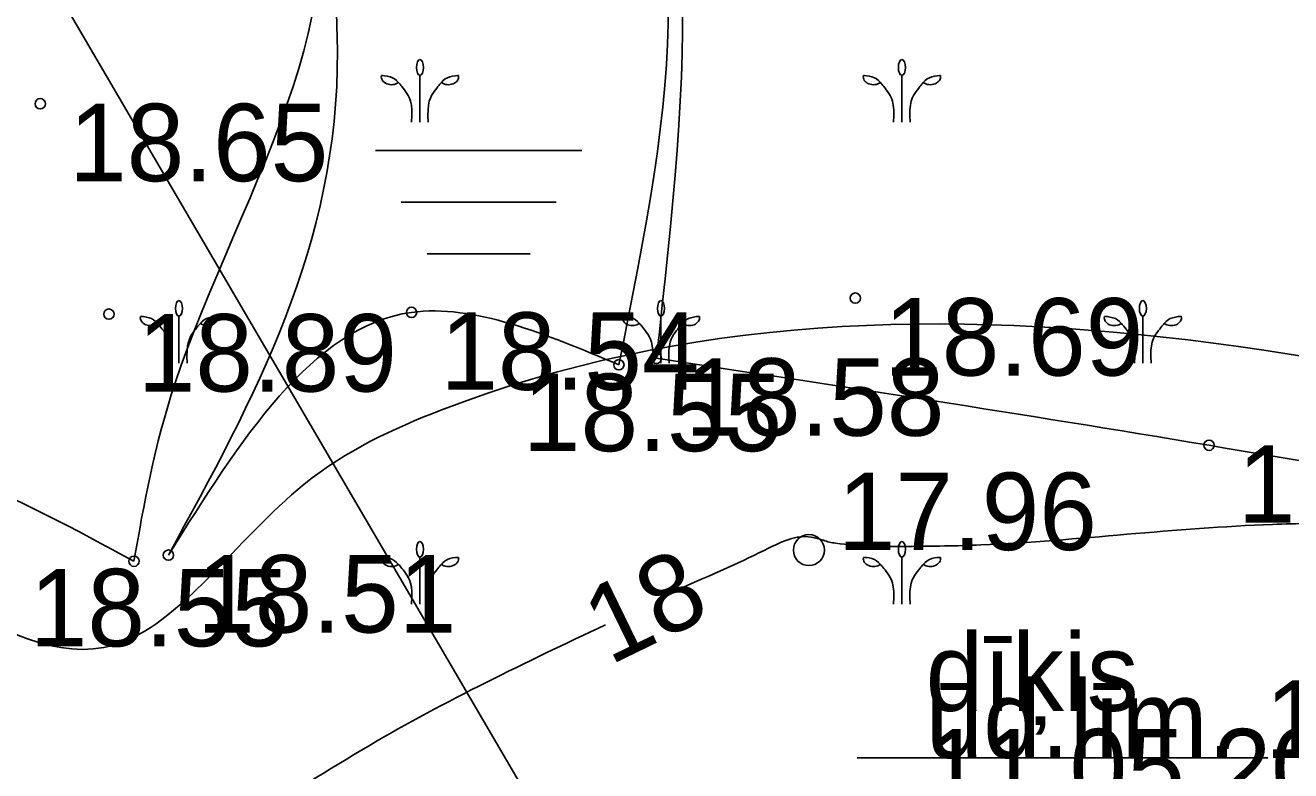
# Model space of a CAD drawing. Extents: x 521824 to 524158, y 294774 to 296228.
# Drawn here: x 522068.27 to 522086.65, y 295999.58 to 296010.41 of the extents above; entities that cross this region are included whole.
import ezdxf

# ---------------------------------------------------------------- set-up
doc = ezdxf.new("R2010")
doc.units = 0
for name, color, linetype in [('GL Aizsargjoslas', 7, 'Continuous'), ('HIDG_AATZ_####_TKST_#', 7, 'Continuous'), ('HIDG_ELEM_####_####_#', 7, 'Continuous'), ('HIDG_HORZ_####_TKST_#', 7, 'Continuous'), ('HIDG_HORZ_PAMT_####_#', 7, 'Continuous'), ('HIDG_HORZ_RESN_####_#', 7, 'Continuous'), ('HIDG_HPAS_####_TKST_#', 7, 'Continuous'), ('HIDG_NLIN_####_####_#', 7, 'Continuous'), ('HIDG_PLIN_####_####_#', 7, 'Continuous'), ('HIDG_UATZ_####_TKST_#', 7, 'Continuous'), ('RELJ_AATZ_####_TKST_#', 7, 'Continuous'), ('RELJ_ELEM_####_####_#', 7, 'Continuous'), ('RELJ_HORZ_PAMT_####_#', 7, 'Continuous'), ('RELJ_NOGA_####_####_#', 7, 'Continuous'), ('RELJ_NOGL_####_####_#', 7, 'Continuous'), ('TERT_ELEM_####_####_#', 7, 'Continuous'), ('TERT_KONT_####_####_#', 7, 'Continuous')]:
    doc.layers.add(name, color=color, linetype=linetype)

msp = doc.modelspace()

# ---------------------------------------------------------------- linework, layer by layer
at = {"layer": 'GL Aizsargjoslas'}
msp.add_lwpolyline([(522131.428, 295816.081), (522115.494, 295836.896), (522093.246, 295865.959), (522070.658, 295896.651), (522048.069, 295927.342), (522034.295, 295950.909), (522016.445, 295981.452), (522014.167, 295985.351), (522007.117, 295997.907), (522041.36, 296024.307), (522061.861, 296026.336), (522066.449, 296014.804), (522085.298, 295982.553), (522098.69, 295959.638), (522141.234, 295901.981), (522163.309, 295873.143), (522185.385, 295844.305), (522186.608, 295842.871), (522172.848, 295833.392), (522161.563, 295826.069), (522160.802, 295825.572), (522154.447, 295832.015)], close=True, dxfattribs=at)
at = {"layer": 'HIDG_ELEM_####_####_#'}
msp.add_circle((522079.65, 296002.784), 0.225, dxfattribs=at)
at = {"layer": 'HIDG_HORZ_PAMT_####_#'}
msp.add_spline([(522097.456, 296003.003), (522098.42, 296003.112), (522098.886, 296003.109), (522101.493, 296002.854), (522104.863, 296002.829), (522105.455, 296002.546), (522105.764, 296002.03), (522106.434, 296001.103), (522105.073, 295999.884), (522105.328, 295997.947), (522105.313, 295997.082), (522105.495, 295995.289), (522105.536, 295995.052), (522105.782, 295994.342), (522106.713, 295993.946), (522107.552, 295993.546), (522108.149, 295993.448), (522108.619, 295991.553), (522108.577, 295991.344), (522108.448, 295991.154), (522106.283, 295991.375), (522105.272, 295992.2), (522104.189, 295992.719), (522103.543, 295992.913), (522103.242, 295993.07), (522101.964, 295993.08), (522101.329, 295993.113), (522100.932, 295993.02), (522099.761, 295992.856), (522098.335, 295992.439), (522097.436, 295991.876), (522096.287, 295991.458), (522094.937, 295990.58), (522094.192, 295990.336), (522093.424, 295990.187), (522091.553, 295990.123), (522089.682, 295990.202), (522089.358, 295990.216), (522085.744, 295990.713), (522081.631, 295990.342), (522080.807, 295990.11), (522079.09, 295989.003), (522078.197, 295988.522), (522077.728, 295988.334), (522077.237, 295988.193), (522076.001, 295988.101), (522074.761, 295988.259), (522072.524, 295989.01), (522071.862, 295989.025), (522071.249, 295988.887), (522068.367, 295988.362), (522067.498, 295988.56), (522067.064, 295988.714), (522066.631, 295988.911), (522064.566, 295990.452), (522063.244, 295992.536), (522063.001, 295993.19), (522062.602, 295994.158), (522059.484, 295999.35), (522058.893, 296002.168), (522061.43, 296003.805), (522064.048, 296003.805), (522069.557, 296001.404), (522072.32, 296003.741), (522074.302, 296004.815), (522097.456, 296003.003)], degree=3, dxfattribs=at)
at = {"layer": 'HIDG_HORZ_RESN_####_#'}
for points in [[(522094.419, 295993.471), (522094.954, 295993.565), (522096.238, 295993.964), (522096.688, 295994.186), (522097.131, 295994.417), (522098.003, 295994.902), (522102.207, 295997.326), (522102.626, 295997.566), (522102.825, 295997.714), (522102.923, 295997.807), (522103.019, 295997.916), (522103.273, 295998.318), (522103.415, 295998.724), (522103.479, 295999.13), (522103.502, 295999.536), (522103.508, 295999.817), (522103.478, 296000.105), (522103.377, 296000.379), (522103.288, 296000.505), (522103.232, 296000.564), (522103.2, 296000.593), (522103.167, 296000.621), (522102.833, 296000.797), (522102.499, 296000.851), (522102.165, 296000.855), (522101.998, 296000.861), (522101.831, 296000.881), (522097.302, 296001.725), (522092.769, 296002.559), (522091.705, 296002.733), (522090.637, 296002.875), (522089.566, 296002.996), (522088.495, 296003.106), (522087.442, 296003.168), (522086.385, 296003.157), (522084.265, 296003.013), (522082.146, 296002.859), (522081.089, 296002.838), (522080.036, 296002.885), (522079.947, 296002.9), (522079.86, 296002.926), (522079.772, 296002.952), (522079.684, 296002.97), (522079.499, 296002.974), (522079.462, 296002.967), (522078.999, 296002.779), (522077.795, 296002.233)], [(522076.693, 296001.698), (522073.251, 295999.937), (522069.684, 295998.285), (522069.633, 295998.28), (522069.496, 295998.301), (522069.359, 295998.339), (522069.222, 295998.38), (522069.086, 295998.409), (522068.72, 295998.453), (522068.449, 295998.318), (522068.414, 295998.223), (522068.385, 295998.128), (522068.338, 295997.938), (522068.282, 295997.558), (522068.247, 295997.178), (522068.2, 295996.798), (522067.729, 295994.059), (522067.268, 295991.321), (522067.299, 295990.913), (522067.497, 295990.535), (522067.816, 295990.195), (522068.007, 295990.042), (522068.108, 295989.971), (522068.212, 295989.903), (522068.971, 295989.627), (522069.729, 295989.648), (522070.549, 295989.787), (522073.982, 295990.519), (522074.567, 295990.609), (522075.157, 295990.665), (522075.749, 295990.722), (522076.337, 295990.814), (522076.713, 295990.923), (522077.072, 295991.098), (522077.582, 295991.652), (522078.55, 295993.97), (522080.388, 295998.378), (522080.481, 295998.539), (522080.583, 295998.609), (522080.81, 295998.515), (522081.314, 295997.644), (522081.814, 295996.353), (522082.223, 295995.227), (522083.472, 295992.047)]]:
    msp.add_spline(points, degree=3, dxfattribs=at)
at = {"layer": 'HIDG_NLIN_####_####_#'}
for points in [[(522069.847, 296002.621), (522070.445, 296005.213), (522071.843, 296012.882), (522070.004, 296013.804), (522068.327, 296014.681), (522064.837, 296015.835), (522066.863, 296015.976), (522068.488, 296015.043), (522072.507, 296013.382), (522076.21, 296014.002), (522077.435, 296005.57)], [(522070.346, 296002.711), (522072.801, 296010.037), (522073.155, 296012.721), (522075.854, 296013.462), (522076.89, 296005.476)]]:
    msp.add_spline(points, degree=3, dxfattribs=at)
at = {"layer": 'HIDG_PLIN_####_####_#'}
for points in [[(522070.346, 296002.711), (522073.878, 296006.237), (522076.89, 296005.476)], [(522077.435, 296005.57), (522085.461, 296004.306), (522098.512, 296003.392), (522105.395, 296003.443), (522107.83, 296000.993), (522105.638, 295997.677), (522105.744, 295995.487), (522109.498, 295993.85), (522109.498, 295989.848), (522114.208, 295986.087), (522123.878, 295989.299), (522133.271, 295980.049), (522137.318, 295976.793), (522131.563, 295972.766), (522130.654, 295969.62), (522124.01, 295968.477), (522115.857, 295969.771), (522111.112, 295969.734), (522110.471, 295975.549), (522112.358, 295978.857), (522112.409, 295984.266), (522101.265, 295992.806), (522096.41, 295991.057), (522092.914, 295989.062)], [(522092.914, 295989.062), (522089.457, 295989.995), (522081.185, 295989.929), (522077.718, 295986.793), (522072.195, 295988.487), (522065.261, 295988.052), (522062.418, 295992.785), (522058.951, 295999.177), (522057.619, 296001.908), (522064.008, 296004.575), (522069.847, 296002.621)]]:
    msp.add_spline(points, degree=3, dxfattribs=at)
at = {"layer": 'HIDG_UATZ_####_TKST_#'}
msp.add_lwpolyline([(522080.35, 295999.765), (522086.316, 295999.765)], dxfattribs=at)
at = {"layer": 'RELJ_ELEM_####_####_#'}
for centre in [(522068.486, 296009.268), (522080.324, 296006.444), (522073.878, 296006.237), (522069.483, 296006.212), (522077.435, 296005.57), (522076.89, 296005.476), (522085.461, 296004.306), (522069.847, 296002.621), (522070.346, 296002.711)]:
    msp.add_circle(centre, 0.075, dxfattribs=at)
at = {"layer": 'RELJ_HORZ_PAMT_####_#'}
for points in [[(522147.001, 296013.879), (522145.334, 296014.111), (522144.908, 296014.079), (522138.003, 296012.088), (522137.814, 296012.008), (522135.146, 296011.271), (522131.635, 296010.287), (522130.341, 296009.639), (522127.864, 296009.75), (522127.714, 296009.761), (522127.564, 296009.8), (522127.264, 296009.832), (522127.105, 296009.79), (522126.615, 296009.677), (522125.425, 296009.552), (522124.235, 296009.457), (522121.853, 296009.334), (522117.084, 296009.201), (522116.821, 296009.194), (522115.322, 296009.109), (522113.823, 296009.021), (522110.825, 296008.845), (522106.552, 296008.587), (522106.42, 296008.498), (522105.24, 296008.381), (522103.71, 296008.042), (522102.575, 296008.01), (522101.436, 296008.101), (522100.295, 296008.227), (522099.156, 296008.295), (522097.506, 296008.302), (522096.685, 296008.185), (522096.274, 296008.062), (522096.069, 296007.981), (522095.864, 296007.884), (522092.757, 296008.408), (522089.948, 296009.718), (522091.502, 296010.619), (522091.012, 296011.544), (522089.457, 296012.256), (522087.875, 296012.556), (522086.266, 296013.266), (522086.078, 296014.194)], [(522045.999, 296008.938), (522046.495, 296008.926), (522047.557, 296008.988), (522048.735, 296009.162), (522050.109, 296009.512), (522050.809, 296009.677), (522052.34, 296009.896), (522053.693, 296010.101), (522054.536, 296010.335), (522054.996, 296010.355), (522055.848, 296010.249), (522056.362, 296010.052), (522056.844, 296009.797), (522057.323, 296009.545), (522057.827, 296009.353), (522058.463, 296009.222), (522059.039, 296009.168), (522060.322, 296008.975), (522060.946, 296008.772), (522061.254, 296008.62), (522061.558, 296008.425), (522061.883, 296008.015), (522062.022, 296007.524), (522062.054, 296007.162), (522062.019, 296006.801), (522061.435, 296005.355), (522061.1, 296005.14), (522060.764, 296004.933), (522060.089, 296004.536), (522058.739, 296003.753), (522057.792, 296003.234), (522057.321, 296002.952), (522057.086, 296002.788), (522056.969, 296002.698), (522056.853, 296002.602), (522056.584, 296002.103), (522056.588, 296001.531), (522056.86, 296000.048), (522057.24, 295998.543), (522057.746, 295997.71), (522058.037, 295997.317), (522058.303, 295996.91), (522059.043, 295995.576), (522059.759, 295994.23), (522060.122, 295993.338), (522060.406, 295992.406), (522060.729, 295991.496), (522060.944, 295991.069), (522061.213, 295990.67), (522061.49, 295990.366), (522061.793, 295990.09), (522062.252, 295989.683), (522062.396, 295989.538), (522064.208, 295987.613), (522065.338, 295986.418), (522065.918, 295985.834), (522066.525, 295985.268), (522067.242, 295984.881), (522068.074, 295984.734), (522068.945, 295984.657), (522069.37, 295984.591), (522069.777, 295984.479), (522071.163, 295983.949), (522071.837, 295983.615), (522072.507, 295983.186), (522073.445, 295982.313), (522074.19, 295981.299), (522074.759, 295980.263), (522075.171, 295979.327), (522075.146, 295979.012), (522074.869, 295978.709), (522073.887, 295978.125), (522072.886, 295977.541), (522072.584, 295977.238), (522072.525, 295976.923), (522072.6, 295976.687), (522072.713, 295976.422), (522073.008, 295976.004)]]:
    msp.add_spline(points, degree=3, dxfattribs=at)
at = {"layer": 'RELJ_NOGA_####_####_#'}
msp.add_spline([(522076.372, 295971.107), (522071.771, 295966.998), (522065.911, 295963.274), (522062.404, 295965.313), (522059.129, 295973.294), (522053.399, 295985.165), (522047.568, 295996.23), (522043.494, 296004.53), (522040.94, 296006.195), (522036.392, 296017.202), (522035.817, 296019.888)], degree=3, dxfattribs=at)
at = {"layer": 'RELJ_NOGL_####_####_#'}
msp.add_spline([(522076.372, 295971.107), (522070.977, 295968.839), (522067.829, 295967.468), (522065.228, 295970.581), (522062.385, 295977.993), (522058.471, 295985.855), (522053.108, 295997.011), (522048.49, 296007.412), (522045.541, 296009.219)], degree=3, dxfattribs=at)
at = {"layer": 'TERT_ELEM_####_####_#'}
for p, q in [((522074, 296009), (522074, 296009.681)), ((522074, 296009), (522074, 296009.681)), ((522081, 296009), (522081, 296009.681)), ((522081, 296009), (522081, 296009.681)), ((522073.353, 296008.588), (522076.353, 296008.588)), ((522073.728, 296007.838), (522075.978, 296007.838)), ((522074.103, 296007.088), (522075.603, 296007.088)), ((522070.5, 296005.5), (522070.5, 296006.181)), ((522070.5, 296005.5), (522070.5, 296006.181)), ((522077.5, 296005.5), (522077.5, 296006.181)), ((522077.5, 296005.5), (522077.5, 296006.181)), ((522084.5, 296005.5), (522084.5, 296006.181)), ((522084.5, 296005.5), (522084.5, 296006.181)), ((522074, 296002), (522074, 296002.681)), ((522074, 296002), (522074, 296002.681)), ((522081, 296002), (522081, 296002.681)), ((522081, 296002), (522081, 296002.681))]:
    msp.add_line(p, q, dxfattribs=at)
for centre in [(522074, 296009.795), (522074, 296009.795), (522081, 296009.795), (522081, 296009.795), (522070.5, 296006.295), (522070.5, 296006.295), (522077.5, 296006.295), (522077.5, 296006.295), (522084.5, 296006.295), (522084.5, 296006.295), (522074, 296002.795), (522074, 296002.795), (522081, 296002.795), (522081, 296002.795)]:
    msp.add_ellipse(centre, major_axis=(0, 0.114), ratio=0.447069, dxfattribs=at)
for centre, major_axis, start_param, end_param in [((522073.586, 296009.658), (-0.147, 0), 6.117242, 8.627806), ((522073.586, 296009.658), (-0.147, 0), 6.117242, 8.627806), ((522074.414, 296009.658), (0.147, 0), 3.938565, 6.449128), ((522074.414, 296009.658), (0.147, 0), 3.938565, 6.449128), ((522080.586, 296009.658), (-0.147, 0), 6.117242, 8.627806), ((522080.586, 296009.658), (-0.147, 0), 6.117242, 8.627806), ((522081.414, 296009.658), (0.147, 0), 3.938565, 6.449128), ((522081.414, 296009.658), (0.147, 0), 3.938565, 6.449128), ((522070.086, 296006.158), (-0.147, 0), 6.117242, 8.627806), ((522070.086, 296006.158), (-0.147, 0), 6.117242, 8.627806), ((522070.914, 296006.158), (0.147, 0), 3.938565, 6.449128), ((522070.914, 296006.158), (0.147, 0), 3.938565, 6.449128), ((522077.086, 296006.158), (-0.147, 0), 6.117242, 8.627806), ((522077.086, 296006.158), (-0.147, 0), 6.117242, 8.627806), ((522077.914, 296006.158), (0.147, 0), 3.938565, 6.449128), ((522077.914, 296006.158), (0.147, 0), 3.938565, 6.449128), ((522084.086, 296006.158), (-0.147, 0), 6.117242, 8.627806), ((522084.086, 296006.158), (-0.147, 0), 6.117242, 8.627806), ((522084.914, 296006.158), (0.147, 0), 3.938565, 6.449128), ((522084.914, 296006.158), (0.147, 0), 3.938565, 6.449128), ((522073.586, 296002.658), (-0.147, 0), 6.117242, 8.627806), ((522073.586, 296002.658), (-0.147, 0), 6.117242, 8.627806), ((522074.414, 296002.658), (0.147, 0), 3.938565, 6.449128), ((522074.414, 296002.658), (0.147, 0), 3.938565, 6.449128), ((522080.586, 296002.658), (-0.147, 0), 6.117242, 8.627806), ((522080.586, 296002.658), (-0.147, 0), 6.117242, 8.627806), ((522081.414, 296002.658), (0.147, 0), 3.938565, 6.449128), ((522081.414, 296002.658), (0.147, 0), 3.938565, 6.449128)]:
    msp.add_ellipse(centre, major_axis=major_axis, ratio=0.769466, start_param=start_param, end_param=end_param, dxfattribs=at)
for points in [[(522073.689, 296009.577), (522073.651, 296009.617), (522073.584, 296009.672), (522073.445, 296009.68), (522073.441, 296009.676)], [(522073.689, 296009.577), (522073.651, 296009.617), (522073.584, 296009.672), (522073.445, 296009.68), (522073.441, 296009.676)], [(522074.311, 296009.577), (522074.349, 296009.617), (522074.417, 296009.672), (522074.555, 296009.68), (522074.559, 296009.676)], [(522074.311, 296009.577), (522074.349, 296009.617), (522074.417, 296009.672), (522074.555, 296009.68), (522074.559, 296009.676)], [(522080.689, 296009.577), (522080.651, 296009.617), (522080.584, 296009.672), (522080.445, 296009.68), (522080.441, 296009.676)], [(522080.689, 296009.577), (522080.651, 296009.617), (522080.584, 296009.672), (522080.445, 296009.68), (522080.441, 296009.676)], [(522081.311, 296009.577), (522081.349, 296009.617), (522081.417, 296009.672), (522081.555, 296009.68), (522081.559, 296009.676)], [(522081.311, 296009.577), (522081.349, 296009.617), (522081.417, 296009.672), (522081.555, 296009.68), (522081.559, 296009.676)], [(522073.879, 296009), (522073.902, 296009.288), (522073.786, 296009.465), (522073.696, 296009.568), (522073.689, 296009.577)], [(522073.879, 296009), (522073.902, 296009.288), (522073.786, 296009.465), (522073.696, 296009.568), (522073.689, 296009.577)], [(522074.121, 296009), (522074.098, 296009.288), (522074.214, 296009.465), (522074.304, 296009.568), (522074.311, 296009.577)], [(522074.121, 296009), (522074.098, 296009.288), (522074.214, 296009.465), (522074.304, 296009.568), (522074.311, 296009.577)], [(522080.879, 296009), (522080.902, 296009.288), (522080.786, 296009.465), (522080.696, 296009.568), (522080.689, 296009.577)], [(522080.879, 296009), (522080.902, 296009.288), (522080.786, 296009.465), (522080.696, 296009.568), (522080.689, 296009.577)], [(522081.121, 296009), (522081.098, 296009.288), (522081.214, 296009.465), (522081.304, 296009.568), (522081.311, 296009.577)], [(522081.121, 296009), (522081.098, 296009.288), (522081.214, 296009.465), (522081.304, 296009.568), (522081.311, 296009.577)], [(522070.189, 296006.077), (522070.151, 296006.117), (522070.084, 296006.172), (522069.945, 296006.18), (522069.941, 296006.176)], [(522070.189, 296006.077), (522070.151, 296006.117), (522070.084, 296006.172), (522069.945, 296006.18), (522069.941, 296006.176)], [(522070.811, 296006.077), (522070.849, 296006.117), (522070.917, 296006.172), (522071.055, 296006.18), (522071.059, 296006.176)], [(522070.811, 296006.077), (522070.849, 296006.117), (522070.917, 296006.172), (522071.055, 296006.18), (522071.059, 296006.176)], [(522077.189, 296006.077), (522077.151, 296006.117), (522077.084, 296006.172), (522076.945, 296006.18), (522076.941, 296006.176)], [(522077.189, 296006.077), (522077.151, 296006.117), (522077.084, 296006.172), (522076.945, 296006.18), (522076.941, 296006.176)], [(522077.811, 296006.077), (522077.849, 296006.117), (522077.917, 296006.172), (522078.055, 296006.18), (522078.059, 296006.176)], [(522077.811, 296006.077), (522077.849, 296006.117), (522077.917, 296006.172), (522078.055, 296006.18), (522078.059, 296006.176)], [(522084.189, 296006.077), (522084.151, 296006.117), (522084.084, 296006.172), (522083.945, 296006.18), (522083.941, 296006.176)], [(522084.189, 296006.077), (522084.151, 296006.117), (522084.084, 296006.172), (522083.945, 296006.18), (522083.941, 296006.176)], [(522084.811, 296006.077), (522084.849, 296006.117), (522084.917, 296006.172), (522085.055, 296006.18), (522085.059, 296006.176)], [(522084.811, 296006.077), (522084.849, 296006.117), (522084.917, 296006.172), (522085.055, 296006.18), (522085.059, 296006.176)], [(522070.379, 296005.5), (522070.402, 296005.788), (522070.286, 296005.965), (522070.196, 296006.068), (522070.189, 296006.077)], [(522070.379, 296005.5), (522070.402, 296005.788), (522070.286, 296005.965), (522070.196, 296006.068), (522070.189, 296006.077)], [(522070.621, 296005.5), (522070.598, 296005.788), (522070.714, 296005.965), (522070.804, 296006.068), (522070.811, 296006.077)], [(522070.621, 296005.5), (522070.598, 296005.788), (522070.714, 296005.965), (522070.804, 296006.068), (522070.811, 296006.077)], [(522077.379, 296005.5), (522077.402, 296005.788), (522077.286, 296005.965), (522077.196, 296006.068), (522077.189, 296006.077)], [(522077.379, 296005.5), (522077.402, 296005.788), (522077.286, 296005.965), (522077.196, 296006.068), (522077.189, 296006.077)], [(522077.621, 296005.5), (522077.598, 296005.788), (522077.714, 296005.965), (522077.804, 296006.068), (522077.811, 296006.077)], [(522077.621, 296005.5), (522077.598, 296005.788), (522077.714, 296005.965), (522077.804, 296006.068), (522077.811, 296006.077)], [(522084.379, 296005.5), (522084.402, 296005.788), (522084.286, 296005.965), (522084.196, 296006.068), (522084.189, 296006.077)], [(522084.379, 296005.5), (522084.402, 296005.788), (522084.286, 296005.965), (522084.196, 296006.068), (522084.189, 296006.077)], [(522084.621, 296005.5), (522084.598, 296005.788), (522084.714, 296005.965), (522084.804, 296006.068), (522084.811, 296006.077)], [(522084.621, 296005.5), (522084.598, 296005.788), (522084.714, 296005.965), (522084.804, 296006.068), (522084.811, 296006.077)], [(522073.689, 296002.577), (522073.651, 296002.617), (522073.584, 296002.672), (522073.445, 296002.68), (522073.441, 296002.676)], [(522073.689, 296002.577), (522073.651, 296002.617), (522073.584, 296002.672), (522073.445, 296002.68), (522073.441, 296002.676)], [(522074.311, 296002.577), (522074.349, 296002.617), (522074.417, 296002.672), (522074.555, 296002.68), (522074.559, 296002.676)], [(522074.311, 296002.577), (522074.349, 296002.617), (522074.417, 296002.672), (522074.555, 296002.68), (522074.559, 296002.676)], [(522080.689, 296002.577), (522080.651, 296002.617), (522080.584, 296002.672), (522080.445, 296002.68), (522080.441, 296002.676)], [(522080.689, 296002.577), (522080.651, 296002.617), (522080.584, 296002.672), (522080.445, 296002.68), (522080.441, 296002.676)], [(522081.311, 296002.577), (522081.349, 296002.617), (522081.417, 296002.672), (522081.555, 296002.68), (522081.559, 296002.676)], [(522081.311, 296002.577), (522081.349, 296002.617), (522081.417, 296002.672), (522081.555, 296002.68), (522081.559, 296002.676)], [(522073.879, 296002), (522073.902, 296002.288), (522073.786, 296002.465), (522073.696, 296002.568), (522073.689, 296002.577)], [(522073.879, 296002), (522073.902, 296002.288), (522073.786, 296002.465), (522073.696, 296002.568), (522073.689, 296002.577)], [(522074.121, 296002), (522074.098, 296002.288), (522074.214, 296002.465), (522074.304, 296002.568), (522074.311, 296002.577)], [(522074.121, 296002), (522074.098, 296002.288), (522074.214, 296002.465), (522074.304, 296002.568), (522074.311, 296002.577)], [(522080.879, 296002), (522080.902, 296002.288), (522080.786, 296002.465), (522080.696, 296002.568), (522080.689, 296002.577)], [(522080.879, 296002), (522080.902, 296002.288), (522080.786, 296002.465), (522080.696, 296002.568), (522080.689, 296002.577)], [(522081.121, 296002), (522081.098, 296002.288), (522081.214, 296002.465), (522081.304, 296002.568), (522081.311, 296002.577)], [(522081.121, 296002), (522081.098, 296002.288), (522081.214, 296002.465), (522081.304, 296002.568), (522081.311, 296002.577)]]:
    msp.add_open_spline(points, degree=3, dxfattribs=at)
at = {"layer": 'TERT_KONT_####_####_#'}
msp.add_spline([(522062.275, 296004.76), (522062.725, 296005.147), (522062.873, 296005.568), (522062.817, 296006.002), (522062.703, 296006.523), (522062.324, 296007.704), (522061.781, 296008.87), (522061.294, 296009.588), (522061.121, 296009.777), (522060.91, 296009.942), (522059.978, 296010.31), (522058.425, 296010.615), (522057.122, 296010.885), (522056.772, 296011.066), (522056.733, 296011.31), (522057.338, 296012.131), (522058.353, 296013.124), (522059.611, 296014.113), (522060.945, 296014.921), (522061.9, 296015.256), (522062.906, 296015.38), (522064.977, 296015.245), (522066.972, 296015.017), (522067.883, 296015.023), (522068.704, 296015.193), (522068.84, 296015.265), (522069.172, 296015.683), (522069.512, 296016.498), (522069.846, 296017.265), (522070.048, 296017.513), (522070.293, 296017.61), (522070.943, 296017.474), (522071.609, 296017.09), (522072.989, 296015.881), (522074.438, 296014.587), (522075.189, 296014.096), (522075.572, 296013.923), (522075.96, 296013.81), (522077.14, 296013.718), (522078.399, 296013.837), (522079.061, 296013.954), (522079.716, 296014.086), (522080.371, 296014.22), (522081.029, 296014.341), (522082.31, 296014.505), (522082.952, 296014.553), (522083.593, 296014.58), (522084.77, 296014.367), (522085.055, 296014.254), (522085.328, 296014.126), (522085.834, 296013.81), (522086.313, 296014.041), (522086.647, 296013.162), (522088.917, 296011.073), (522090.338, 296009.591), (522091.73, 296008.067), (522092.394, 296007.257), (522093.014, 296006.421), (522093.66, 296005.598), (522094.014, 296005.204), (522094.401, 296004.827), (522095.35, 296004.152), (522096.396, 296003.67), (522096.943, 296003.478)], degree=3, dxfattribs=at)

# ---------------------------------------------------------------- texts
at = {"layer": 'HIDG_AATZ_####_TKST_#'}
msp.add_text(' 17.96', height=1.125, dxfattribs=at).set_placement((522079.65, 296002.784))
at = {"layer": 'HIDG_HORZ_####_TKST_#'}
msp.add_text('18', height=1.125, rotation=25.9448, dxfattribs=at).set_placement((522076.755, 296001.105))
at = {"layer": 'HIDG_HPAS_####_TKST_#'}
msp.add_text('dīķis', height=1.125, dxfattribs=at).set_placement((522081.345, 296000.448))
at = {"layer": 'HIDG_UATZ_####_TKST_#'}
for s, p in [('ūd.līm. 18.54', (522081.345, 295999.765)), ('11.05.20', (522081.345, 295999.061))]:
    msp.add_text(s, height=1.125, dxfattribs=at).set_placement(p)
at = {"layer": 'RELJ_AATZ_####_TKST_#'}
for s, p in [(' 18.65', (522068.486, 296008.143)), (' 18.69', (522080.324, 296005.319)), (' 18.89', (522069.483, 296005.087)), (' 18.54', (522073.878, 296005.112)), (' 18.58', (522077.435, 296004.445)), (' 18.55', (522075.078, 296004.221)), (' 18.56', (522085.461, 296003.181)), (' 18.51', (522070.346, 296001.586)), (' 18.55', (522067.915, 296001.386))]:
    msp.add_text(s, height=1.125, dxfattribs=at).set_placement(p)

doc.saveas('drawing.dxf')
